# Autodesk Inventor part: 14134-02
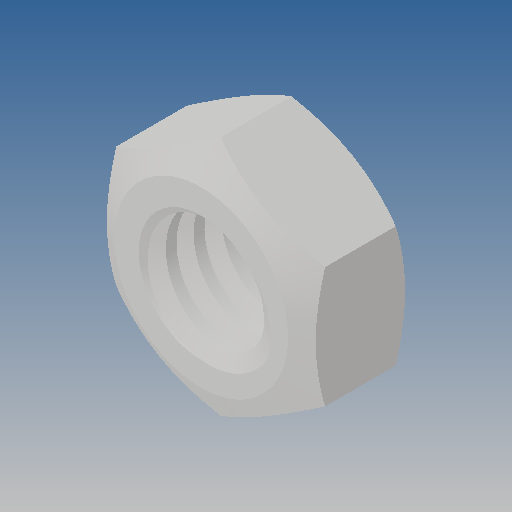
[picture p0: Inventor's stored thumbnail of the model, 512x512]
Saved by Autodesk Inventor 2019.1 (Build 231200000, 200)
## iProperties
Created: 2012-01
Part Number: 14134-02
Material: Ogólny
Document SubType Name: Modeling
Designer: CADENGINEERING4
Density: 1 g/cm^3
Appearance: Domyślna
Author: CADENGINEERING4
Revision Number: ÈÎºÎ
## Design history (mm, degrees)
feature "ÇÐ³ý-É¨Ãè1"
node "Bryła1"
